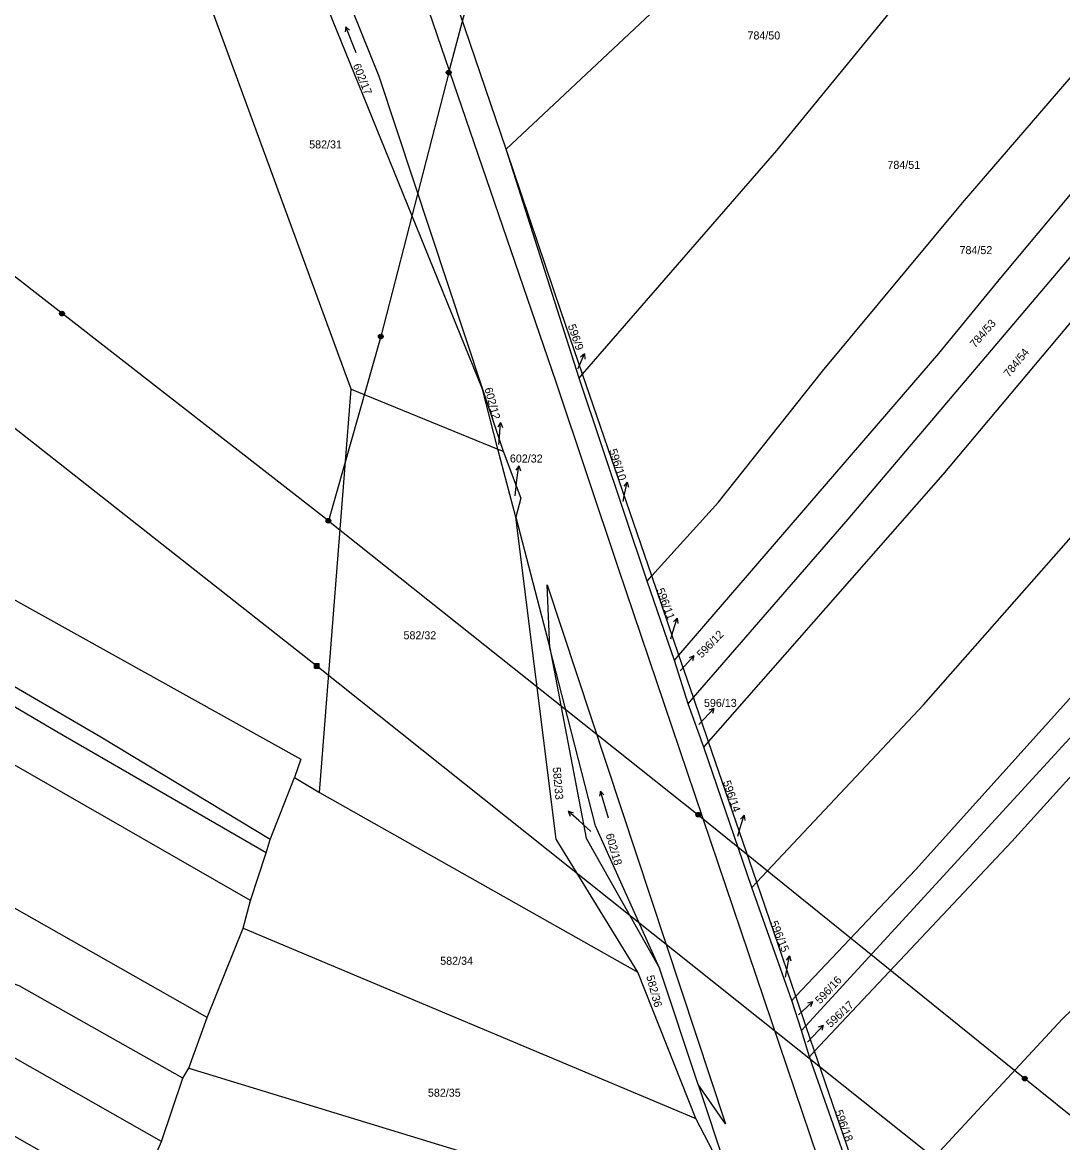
# Model space of a CAD drawing. Extents: x -757266 to -753360, y -1162585 to -1157740.
# Drawn here: x -756745.7 to -756524.8, y -1160423.5 to -1160185.6 of the extents above; entities that cross this region are included whole.
import ezdxf

# ---------------------------------------------------------------- set-up
doc = ezdxf.new("R2010")
doc.units = 0
for name, color, linetype in [('Hranice parcel', 7, 'Continuous'), ('Parcelní čísla', 7, 'Continuous'), ('Pop  PČ popisy', 7, 'Continuous'), ('Poz předměty', 7, 'Continuous'), ('Značky kultur', 7, 'Continuous')]:
    doc.layers.add(name, color=color, linetype=linetype)

msp = doc.modelspace()

# ---------------------------------------------------------------- linework, layer by layer
at = {"layer": 'Hranice parcel'}
for p, q in [((-756675.89, -1160263.5), (-756716.37, -1160153.06)), ((-756643, -1160212.54), (-756655.39, -1160175.98)), ((-756627.48, -1160261.15), (-756643, -1160212.54)), ((-756627.48, -1160261.15), (-756626.75, -1160260.31)), ((-756613.07, -1160304.25), (-756627.48, -1160261.15)), ((-756612.07, -1160303.14), (-756626.75, -1160260.31)), ((-756682.66, -1160349.16), (-756675.89, -1160263.5)), ((-756675.89, -1160263.5), (-756644.77, -1160276.22)), ((-756648.03, -1160263.48), (-756643.65, -1160276.68)), ((-756644.77, -1160276.22), (-756648.03, -1160263.48)), ((-756644.77, -1160276.22), (-756643.65, -1160276.68)), ((-756640.95, -1160290.69), (-756644.77, -1160276.22)), ((-756640.95, -1160290.69), (-756633.73, -1160318.45)), ((-756613.07, -1160304.25), (-756612.07, -1160303.14)), ((-756607.24, -1160321.1), (-756613.07, -1160304.25)), ((-756606.29, -1160320), (-756612.07, -1160303.14)), ((-756607.24, -1160321.1), (-756606.29, -1160320)), ((-756604.33, -1160330.28), (-756607.24, -1160321.1)), ((-756603.21, -1160328.99), (-756606.29, -1160320)), ((-756604.33, -1160330.28), (-756603.21, -1160328.99)), ((-756601.02, -1160339.53), (-756604.33, -1160330.28)), ((-756600, -1160338.36), (-756603.21, -1160328.99)), ((-756601.02, -1160339.53), (-756600, -1160338.36)), ((-756590.8, -1160369.29), (-756601.02, -1160339.53)), ((-756589.77, -1160368.2), (-756600, -1160338.36)), ((-756693.1, -1160359.12), (-756687.93, -1160345.95)), ((-756687.93, -1160345.95), (-756682.66, -1160349.16)), ((-756682.66, -1160349.16), (-756615.03, -1160387.34)), ((-756693.96, -1160361.99), (-756693.1, -1160359.12)), ((-756697.27, -1160372.06), (-756693.96, -1160361.99)), ((-756590.8, -1160369.29), (-756589.77, -1160368.2)), ((-756581.47, -1160392.42), (-756589.77, -1160368.2)), ((-756582.32, -1160393.32), (-756590.8, -1160369.29)), ((-756698.85, -1160377.95), (-756697.27, -1160372.06)), ((-756706.5, -1160396.92), (-756698.85, -1160377.95)), ((-756698.85, -1160377.95), (-756602.71, -1160418.42)), ((-756602.71, -1160418.42), (-756615.03, -1160387.34)), ((-756602.19, -1160411.19), (-756610.42, -1160386.47)), ((-756582.32, -1160393.32), (-756581.47, -1160392.42)), ((-756579.32, -1160398.69), (-756581.47, -1160392.42)), ((-756580.23, -1160399.68), (-756582.32, -1160393.32)), ((-756710.35, -1160407.71), (-756706.5, -1160396.92)), ((-756580.23, -1160399.68), (-756579.32, -1160398.69)), ((-756578.59, -1160405.26), (-756580.23, -1160399.68)), ((-756577.47, -1160404.07), (-756579.32, -1160398.69)), ((-756578.59, -1160405.26), (-756577.47, -1160404.07)), ((-756565.84, -1160441.42), (-756578.59, -1160405.26)), ((-756711.67, -1160409.79), (-756710.35, -1160407.71)), ((-756710.35, -1160407.71), (-756591.25, -1160444.04)), ((-756716.21, -1160423.27), (-756711.67, -1160409.79)), ((-756602.19, -1160411.19), (-756594.76, -1160433.49)), ((-756759.97, -1160414.94), (-756740.72, -1160425.98)), ((-756594.76, -1160433.49), (-756602.71, -1160418.42)), ((-756718.4, -1160428.27), (-756716.21, -1160423.27))]:
    msp.add_line(p, q, dxfattribs=at)
for points in [[(-756643, -1160212.54), (-756586.21, -1160159.2), (-756563.95, -1160134.41)], [(-756691.35, -1160144.02), (-756670.01, -1160197.02), (-756648.03, -1160263.48)], [(-756626.75, -1160260.31), (-756585.5, -1160212.79), (-756559.67, -1160181.22), (-756531.33, -1160145.51)], [(-756648.03, -1160263.48), (-756681.74, -1160180.46), (-756692.48, -1160161.42), (-756714.53, -1160152.53)], [(-756571.91, -1160441.17), (-756619.15, -1160301.58), (-756632.35, -1160262.03), (-756668.08, -1160157.81)], [(-756612.07, -1160303.14), (-756597.92, -1160287.45), (-756575.81, -1160259.66), (-756546.05, -1160223.88), (-756518.07, -1160191.45), (-756492.8, -1160159.61)], [(-756606.29, -1160320), (-756551.09, -1160255.9), (-756537.89, -1160239.82), (-756514.48, -1160211.78), (-756499.89, -1160194.01), (-756474.32, -1160165.39)], [(-756603.21, -1160328.99), (-756570.38, -1160291.11), (-756516.2, -1160227.25), (-756465.2, -1160168.86)], [(-756600, -1160338.36), (-756550.17, -1160281.57), (-756507.98, -1160231.33), (-756479.36, -1160198.95), (-756456.82, -1160171.92)], [(-756589.77, -1160368.2), (-756554.35, -1160330.52), (-756481.21, -1160247.51), (-756426.16, -1160180.16)], [(-756581.47, -1160392.42), (-756556.05, -1160365.57), (-756502.87, -1160306.55), (-756399.92, -1160191.29)], [(-756579.32, -1160398.69), (-756518.62, -1160332.51), (-756446.42, -1160252.68), (-756393.31, -1160193.12)], [(-756577.47, -1160404.07), (-756535.61, -1160359.58), (-756476.82, -1160294.64), (-756446.21, -1160262.26), (-756385.01, -1160195.93)], [(-756626.75, -1160260.31), (-756631.29, -1160247.07), (-756643, -1160212.54)], [(-756564.34, -1160439.83), (-756524.89, -1160397.27), (-756508.04, -1160380.97), (-756490.27, -1160361.41), (-756400.01, -1160267.91), (-756351.25, -1160219.36)], [(-756836.6, -1160273.01), (-756826.62, -1160262.6), (-756802.25, -1160276.82), (-756758.7, -1160302.02), (-756686.63, -1160342.06), (-756687.93, -1160345.95)], [(-756693.1, -1160359.12), (-756729.05, -1160337.36), (-756777.68, -1160309.08), (-756836.6, -1160273.01)], [(-756693.96, -1160361.99), (-756738.43, -1160336.23), (-756791.75, -1160304.88), (-756838.82, -1160275.99)], [(-756643.65, -1160276.68), (-756639.87, -1160286.65), (-756640.95, -1160290.69)], [(-756697.27, -1160372.06), (-756762.83, -1160334.49), (-756812.59, -1160305.56), (-756845.3, -1160284.87)], [(-756615.03, -1160387.34), (-756632.37, -1160359.08), (-756640.95, -1160290.69)], [(-756706.5, -1160396.92), (-756782.06, -1160354.11), (-756813.4, -1160335.52), (-756827.13, -1160328.09), (-756848.94, -1160315.16), (-756868.5, -1160304.23)], [(-756633.73, -1160318.45), (-756634.31, -1160305.06), (-756596.37, -1160419.54), (-756602.19, -1160411.19)], [(-756711.67, -1160409.79), (-756746.39, -1160390.2), (-756750.73, -1160388.75), (-756778.91, -1160372), (-756828.65, -1160343.34), (-756858.27, -1160326.75), (-756880.96, -1160312.2)], [(-756633.73, -1160318.45), (-756625.98, -1160358.88), (-756610.42, -1160386.47)], [(-756610.42, -1160386.47), (-756623.98, -1160356.26), (-756629.87, -1160333.27), (-756633.73, -1160318.45)], [(-756716.21, -1160423.27), (-756809.79, -1160370.08), (-756860.54, -1160341.13), (-756881.24, -1160327.57)], [(-756564.34, -1160439.83), (-756565.97, -1160437.61), (-756577.47, -1160404.07)]]:
    msp.add_lwpolyline(points, dxfattribs=at)
at = {"layer": 'Pop  PČ popisy'}
for p, q in [((-756627.54, -1160258.74), (-756626.319, -1160255.998)), ((-756626.319, -1160255.998), (-756627.184, -1160256.71)), ((-756626.319, -1160255.998), (-756626.269, -1160257.117)), ((-756627.74, -1160259.19), (-756627.54, -1160258.74)), ((-756644.168, -1160270.59), (-756644.755, -1160271.544)), ((-756644.43, -1160273.58), (-756644.168, -1160270.59)), ((-756644.168, -1160270.59), (-756643.757, -1160271.632)), ((-756644.56, -1160275.21), (-756644.43, -1160273.58)), ((-756640.324, -1160279.781), (-756640.943, -1160280.714)), ((-756640.69, -1160282.76), (-756640.324, -1160279.781)), ((-756640.324, -1160279.781), (-756639.949, -1160280.836)), ((-756641.09, -1160286.16), (-756640.69, -1160282.76)), ((-756617.317, -1160283.204), (-756618, -1160284.092)), ((-756617.89, -1160286.15), (-756617.317, -1160283.204)), ((-756617.317, -1160283.204), (-756617.017, -1160284.283)), ((-756618.12, -1160287.33), (-756617.89, -1160286.15)), ((-756607.56, -1160314.99), (-756606.683, -1160312.12)), ((-756606.683, -1160312.12), (-756607.454, -1160312.931)), ((-756606.683, -1160312.12), (-756606.497, -1160313.224)), ((-756608.04, -1160316.54), (-756607.56, -1160314.99)), ((-756605.11, -1160322.33), (-756603.102, -1160320.1)), ((-756603.102, -1160320.1), (-756604.144, -1160320.509)), ((-756603.102, -1160320.1), (-756603.4, -1160321.179)), ((-756606.02, -1160323.33), (-756605.11, -1160322.33)), ((-756600.92, -1160333.49), (-756598.873, -1160331.295)), ((-756598.873, -1160331.295), (-756599.923, -1160331.686)), ((-756598.873, -1160331.295), (-756599.19, -1160332.369)), ((-756602.07, -1160334.71), (-756600.92, -1160333.49)), ((-756627.57, -1160355.12), (-756629.8, -1160353.112)), ((-756629.8, -1160353.112), (-756628.721, -1160353.41)), ((-756629.8, -1160353.112), (-756629.391, -1160354.154)), ((-756593.33, -1160356.85), (-756592.453, -1160353.98)), ((-756592.453, -1160353.98), (-756593.224, -1160354.791)), ((-756592.453, -1160353.98), (-756592.267, -1160355.084)), ((-756625, -1160357.45), (-756627.57, -1160355.12)), ((-756593.81, -1160358.39), (-756593.33, -1160356.85)), ((-756582.807, -1160383.844), (-756583.49, -1160384.732)), ((-756583.38, -1160386.79), (-756582.807, -1160383.844)), ((-756582.807, -1160383.844), (-756582.507, -1160384.923)), ((-756583.68, -1160388.35), (-756583.38, -1160386.79)), ((-756580.14, -1160395.64), (-756577.945, -1160393.593)), ((-756577.945, -1160393.593), (-756579.019, -1160393.91)), ((-756577.945, -1160393.593), (-756578.336, -1160394.643)), ((-756580.93, -1160396.36), (-756580.14, -1160395.64)), ((-756577.7, -1160400.8), (-756575.653, -1160398.605)), ((-756575.653, -1160398.605), (-756576.703, -1160398.996)), ((-756575.653, -1160398.605), (-756575.97, -1160399.679)), ((-756578.95, -1160402.15), (-756577.7, -1160400.8))]:
    msp.add_line(p, q, dxfattribs=at)
at = {"layer": 'Poz předměty'}
for p, q in [((-756655.19, -1160196.23), (-756634.19, -1160117.54)), ((-756874.39, -1160171.69), (-756683.22, -1160322.27)), ((-756737.32, -1160247.42), (-756807.88, -1160192.32)), ((-756655.19, -1160196.23), (-756669.63, -1160252.3)), ((-756680.73, -1160291.42), (-756737.32, -1160247.42)), ((-756669.63, -1160252.3), (-756680.73, -1160291.42)), ((-756680.73, -1160291.42), (-756602.19, -1160353.86)), ((-756683.722, -1160321.769), (-756682.721, -1160321.769)), ((-756683.722, -1160322.769), (-756683.722, -1160321.769)), ((-756683.722, -1160321.969), (-756682.721, -1160321.969)), ((-756683.722, -1160322.169), (-756682.721, -1160322.169)), ((-756683.722, -1160322.369), (-756682.721, -1160322.369)), ((-756683.722, -1160322.569), (-756682.721, -1160322.569)), ((-756683.722, -1160322.769), (-756682.721, -1160322.769)), ((-756683.521, -1160322.769), (-756683.521, -1160321.769)), ((-756683.322, -1160322.769), (-756683.322, -1160321.769)), ((-756683.22, -1160322.27), (-756484.87, -1160480.2)), ((-756683.121, -1160322.769), (-756683.121, -1160321.769)), ((-756682.922, -1160322.769), (-756682.922, -1160321.769)), ((-756682.721, -1160322.769), (-756682.721, -1160321.769)), ((-756602.19, -1160353.86), (-756532.85, -1160409.89)), ((-756532.85, -1160409.89), (-756473.11, -1160457.82))]:
    msp.add_line(p, q, dxfattribs=at)
for centre, radius in [((-756655.1934, -1160196.2299), 0.5), ((-756655.1934, -1160196.2299), 0.4), ((-756655.1934, -1160196.2299), 0.3), ((-756655.1934, -1160196.2299), 0.2), ((-756655.1934, -1160196.2299), 0.1), ((-756737.3234, -1160247.4199), 0.5), ((-756737.3234, -1160247.4199), 0.4), ((-756737.3234, -1160247.4199), 0.3), ((-756737.3234, -1160247.4199), 0.2), ((-756737.3234, -1160247.4199), 0.1), ((-756669.6334, -1160252.2999), 0.5), ((-756669.6334, -1160252.2999), 0.4), ((-756669.6334, -1160252.2999), 0.3), ((-756669.6334, -1160252.2999), 0.2), ((-756669.6334, -1160252.2999), 0.1), ((-756680.7334, -1160291.4199), 0.5), ((-756680.7334, -1160291.4199), 0.4), ((-756680.7334, -1160291.4199), 0.3), ((-756680.7334, -1160291.4199), 0.2), ((-756680.7334, -1160291.4199), 0.1), ((-756602.1934, -1160353.8599), 0.5), ((-756602.1934, -1160353.8599), 0.4), ((-756602.1934, -1160353.8599), 0.3), ((-756602.1934, -1160353.8599), 0.2), ((-756602.1934, -1160353.8599), 0.1), ((-756532.8534, -1160409.8899), 0.5), ((-756532.8534, -1160409.8899), 0.4), ((-756532.8534, -1160409.8899), 0.3), ((-756532.8534, -1160409.8899), 0.2), ((-756532.8534, -1160409.8899), 0.1)]:
    msp.add_circle(centre, radius, dxfattribs=at)
at = {"layer": 'Značky kultur'}
for p, q in [((-756677.072, -1160186.499), (-756677.171, -1160187.593)), ((-756674.825, -1160192.062), (-756677.072, -1160186.499)), ((-756677.072, -1160186.499), (-756676.241, -1160187.218)), ((-756622.984, -1160348.832), (-756623.178, -1160349.913)), ((-756621.23, -1160354.57), (-756622.984, -1160348.832)), ((-756622.984, -1160348.832), (-756622.219, -1160349.62))]:
    msp.add_line(p, q, dxfattribs=at)

# ---------------------------------------------------------------- texts
at = {"layer": 'Parcelní čísla'}
for s, p in [('784/50', (-756591.73, -1160189.21)), ('582/31', (-756684.82, -1160212.35)), ('784/51', (-756562.01, -1160216.69)), ('784/52', (-756546.69, -1160234.8)), ('602/32', (-756642.19, -1160279.06)), ('582/32', (-756664.79, -1160316.6)), ('596/13', (-756600.97, -1160330.97)), ('582/34', (-756656.99, -1160385.74)), ('582/35', (-756659.6, -1160413.76))]:
    msp.add_text(s, height=1.7, dxfattribs=at).set_placement(p)
for s, rotation, p in [('602/17', 292, (-756675.588, -1160194.708)), ('596/9', 289, (-756629.923, -1160250.006)), ('784/53', 49, (-756543.398, -1160254.827)), ('784/54', 51, (-756536.169, -1160261.074)), ('602/12', 285, (-756647.611, -1160263.359)), ('596/10', 288, (-756621.158, -1160276.452)), ('596/11', 290.999997, (-756611.123, -1160306.104)), ('596/12', 46, (-756601.468, -1160320.71)), ('582/33', 275, (-756633.114, -1160343.818)), ('596/14', 289, (-756597.003, -1160346.916)), ('602/18', 286, (-756621.867, -1160358.094)), ('596/15', 292, (-756586.968, -1160376.788)), ('582/36', 285, (-756613.251, -1160388.199)), ('596/16', 47, (-756576.308, -1160394.189)), ('596/17', 43, (-756574.09, -1160399.211)), ('596/18', 290, (-756573.208, -1160416.91))]:
    msp.add_text(s, height=1.7, rotation=rotation, dxfattribs=at).set_placement(p)

doc.saveas('drawing.dxf')
